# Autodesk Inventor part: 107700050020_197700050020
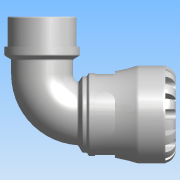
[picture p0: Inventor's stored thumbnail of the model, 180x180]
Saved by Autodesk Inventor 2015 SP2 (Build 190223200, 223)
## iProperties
Created: 2016-12
Part Number: 107700050020_197700050020
Material: PVC-Piping
Description: PLASSON 90° ELBOW WITH MALE INTEGRAL BRASS 50X2" SERIES 1
Document SubType Name: Modeling
Designer: KIM
Mass: 664.223 g
Surface Area: 733.008 cm^2
Volume: 474.445 cm^3
Density: 1.4 g/cm^3
Appearance: Smooth - White
Author: KIM
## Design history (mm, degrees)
derived "1077.ipt"
feature "Solid1::1077.ipt"
tag "TaggingFeature1"
body "Solid1"
other parameters: "d1" = 33.18, "d3" = 62.5, "d4" = 85, "d8" = 72.25, "d13" = 9, "d14" = 9, "d15" = 0, "d17" = 360 deg, "d19" = 8 deg, "d20" = 1, "d21" = 1, "d22" = 8 deg, "d24" = 0, "d26" = 360 deg, "d33" = 8.5, "d43" = 66.3, "d51" = 0.85, "d54" = 17.5, "d55" = 11, "d57" = 17.64, "d58" = 0, "d74" = 0, "d78" = 79, "d82" = 1, "d115" = 360 deg, "d207" = 90 deg, "d228" = 14.875, "d247" = 1.7, "d248" = 4.74, "d268" = 39.7375, "d269" = 4.74, "d270" = 116, "d276" = 59.614, "d277" = 26, "d278" = 65.5754, "d279" = 85, "d280" = 33.8, "d281" = 8.9421, "d283" = 53.6526, "d286" = 0, "d287" = 0, "d288" = 41.7298, "d290" = 6.3237, "d292" = 30 deg, "d294" = 5.9614, "d296" = 30 deg, "E_" = 85, "l_" = 79, "A_" = 116, "A_1" = 85, "l_2" = 26, "R_" = 59.614, "d9" = 11.25, "d11" = 85, "d12" = 62.5, "d289" = 41.7298
